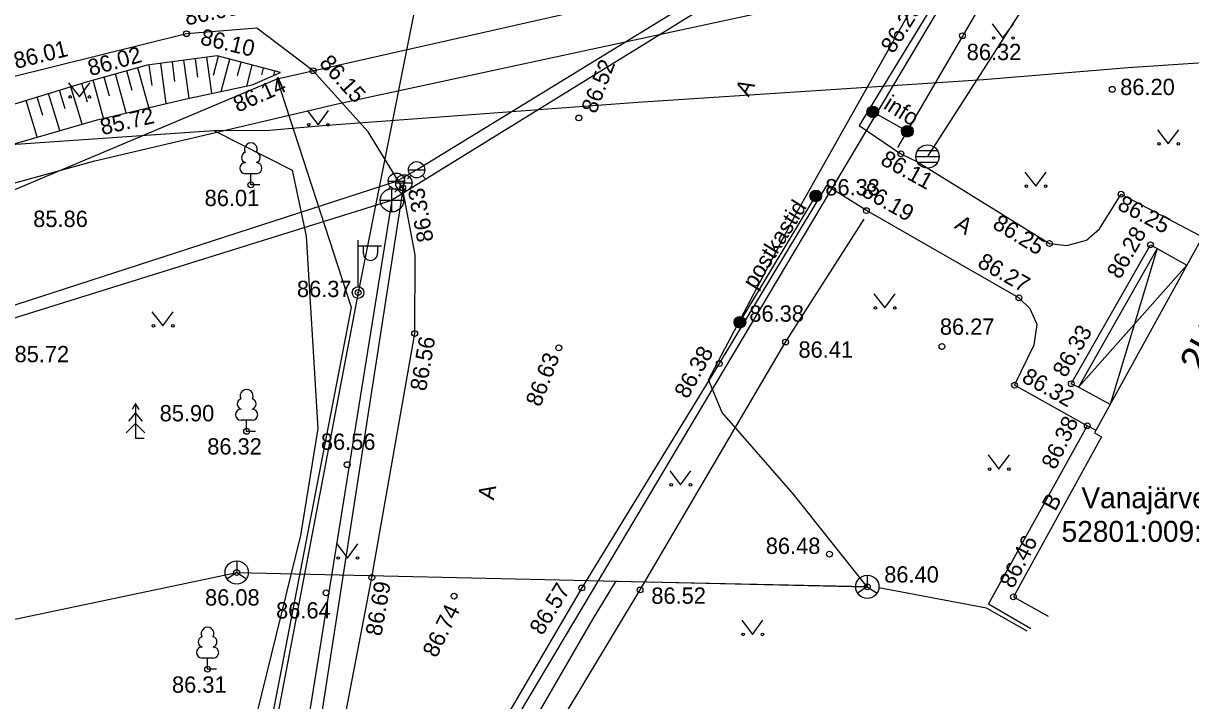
# Model space of a CAD drawing. Extents: x 648748 to 649126, y 6457789 to 6458252.
# Drawn here: x 648959.4 to 649009.5, y 6458116.3 to 6458145.4 of the extents above; entities that cross this region are included whole.
import ezdxf

# ---------------------------------------------------------------- set-up
doc = ezdxf.new("R2010")
doc.units = 0
for name, color, linetype in [('HALJASTUS', 7, 'Continuous'), ('HOONE', 7, 'Continuous'), ('HOONEDET', 7, 'Continuous'), ('KKAEV', 7, 'Continuous'), ('KORGUS-EH2000', 7, 'Continuous'), ('KTRASS', 7, 'Continuous'), ('MPOHULIIN', 7, 'Continuous'), ('PIIR', 7, 'Continuous'), ('POST', 7, 'Continuous'), ('PUU', 7, 'Continuous'), ('RAJATIS', 7, 'Continuous'), ('RELJEEF', 7, 'Continuous'), ('SIKAEV', 7, 'Continuous'), ('SITRASS', 7, 'Continuous'), ('SKKAEV', 7, 'Continuous'), ('SKTRASS', 7, 'Continuous'), ('TEE', 7, 'Continuous'), ('VKAEV', 7, 'Continuous'), ('VTRASS', 7, 'Continuous')]:
    doc.layers.add(name, color=color, linetype=linetype)

msp = doc.modelspace()

# ---------------------------------------------------------------- linework, layer by layer
at = {"layer": 'HALJASTUS'}
for p, q in [((649001.002, 6458145.339), (649001.465, 6458144.733)), ((649001.465, 6458144.733), (649001.911, 6458145.339)), ((648961.368, 6458142.814), (648961.832, 6458142.208)), ((648961.832, 6458142.208), (648962.277, 6458142.814)), ((648971.609, 6458141.622), (648972.072, 6458141.015)), ((648972.072, 6458141.015), (648972.518, 6458141.622)), ((649008.096, 6458140.802), (649008.56, 6458140.195)), ((649008.56, 6458140.195), (649009.005, 6458140.802)), ((649002.404, 6458138.987), (649002.868, 6458138.38)), ((649002.868, 6458138.38), (649003.313, 6458138.987)), ((648995.927, 6458133.763), (648996.391, 6458133.157)), ((648996.391, 6458133.157), (648996.836, 6458133.763)), ((648964.945, 6458132.995), (648965.409, 6458132.388)), ((648965.409, 6458132.388), (648965.854, 6458132.995)), ((649000.828, 6458126.848), (649001.292, 6458126.242)), ((649001.292, 6458126.242), (649001.737, 6458126.848)), ((648987.163, 6458126.174), (648987.626, 6458125.568)), ((648987.626, 6458125.568), (648988.072, 6458126.174)), ((648972.871, 6458123.035), (648973.335, 6458122.428)), ((648973.335, 6458122.428), (648973.78, 6458123.035)), ((648990.253, 6458119.76), (648990.716, 6458119.153)), ((648990.716, 6458119.153), (648991.162, 6458119.76))]:
    msp.add_line(p, q, dxfattribs=at)
for points in [[(648996.956, 6458140.042), (649002.443, 6458149.457), (649002.965, 6458149.902), (649013.289, 6458150.815), (649022.182, 6458151.711), (649026.81, 6458151.999), (649025.182, 6458145.874), (649024.817, 6458144.814)], [(648995.014, 6458108.651), (648992.555, 6458109.206), (648980.179, 6458111.553), (648985.889, 6458121.059), (648992.136, 6458131.694), (648995.514, 6458136.968)]]:
    msp.add_lwpolyline(points, dxfattribs=at)
for centre in [(649001.064, 6458144.733), (649001.893, 6458144.733), (648961.431, 6458142.208), (648962.26, 6458142.208), (648971.671, 6458141.015), (648972.5, 6458141.015), (649008.159, 6458140.195), (649008.988, 6458140.195), (649002.467, 6458138.38), (649003.296, 6458138.38), (648995.99, 6458133.157), (648996.819, 6458133.157), (648965.008, 6458132.388), (648965.837, 6458132.388), (649000.891, 6458126.242), (649001.72, 6458126.242), (648987.225, 6458125.568), (648988.054, 6458125.568), (648972.934, 6458122.428), (648973.763, 6458122.428), (648990.315, 6458119.153), (648991.144, 6458119.153)]:
    msp.add_circle(centre, 0.055, dxfattribs=at)
at = {"layer": 'HOONE'}
for points in [[(649018.559, 6458140.403), (649014.12, 6458142.878), (649010.319, 6458136.06), (649010.026, 6458136.209), (649005.386, 6458127.796), (649005.695, 6458127.625), (649001.912, 6458120.767), (649003.41, 6458119.934)], [(649006.059, 6458129.017), (649004.709, 6458129.762), (649004.395, 6458129.906), (649007.793, 6458135.863), (649008.077, 6458135.702), (649009.357, 6458134.996)]]:
    msp.add_lwpolyline(points, dxfattribs=at)
at = {"layer": 'HOONEDET'}
for p, q in [((649008.077, 6458135.702), (649004.709, 6458129.762)), ((649008.077, 6458135.702), (649006.059, 6458129.017)), ((649004.709, 6458129.762), (649009.357, 6458134.996))]:
    msp.add_line(p, q, dxfattribs=at)
msp.add_lwpolyline([(649005.449, 6458127.911), (649005.083, 6458128.103), (649000.84, 6458120.461), (649002.663, 6458119.409)], dxfattribs=at)
at = {"layer": 'KKAEV'}
for p, q in [((648975.244, 6458137.272), (648975.244, 6458138.272)), ((648974.744, 6458137.772), (648975.744, 6458137.772))]:
    msp.add_line(p, q, dxfattribs=at)
msp.add_circle((648975.244, 6458137.772), 0.5, dxfattribs=at)
at = {"layer": 'KORGUS-EH2000'}
for centre in [(648966.422, 6458144.919), (648999.73, 6458144.834), (648971.86, 6458143.333), (649006.156, 6458142.534), (648983.261, 6458141.306), (648997.086, 6458139.766), (648969.19, 6458138.438), (648975.702, 6458138.304), (649006.534, 6458138.037), (648995.602, 6458137.331), (649003.459, 6458135.922), (649007.793, 6458135.863), (648973.79, 6458133.816), (649002.15, 6458133.592), (648976.218, 6458132.059), (648992.136, 6458131.694), (648982.402, 6458131.443), (648998.845, 6458131.505), (648989.291, 6458130.767), (649001.962, 6458129.843), (649004.395, 6458129.906), (648969.007, 6458127.863), (649005.083, 6458128.103), (648973.323, 6458126.434), (648994.017, 6458122.596), (648968.579, 6458121.81), (648974.38, 6458121.59), (648995.643, 6458121.195), (648972.416, 6458120.936), (648977.908, 6458120.791), (648983.389, 6458121.145), (648985.889, 6458121.059), (649001.912, 6458120.767), (648967.331, 6458117.663)]:
    msp.add_circle(centre, 0.125, dxfattribs=at)
at = {"layer": 'KTRASS'}
for p, q in [((649000.53, 6458153.406), (648975.244, 6458137.772)), ((648957.262, 6458132.173), (648975.244, 6458137.772)), ((648975.244, 6458137.772), (648970.422, 6458107.842))]:
    msp.add_line(p, q, dxfattribs=at)
at = {"layer": 'MPOHULIIN'}
msp.add_lwpolyline([(648980.689, 6458168.372), (648973.79, 6458133.816), (648969.428, 6458110.939), (648964.567, 6458086.1), (648960.388, 6458067.751), (648949.192, 6458062.065)], dxfattribs=at)
at = {"layer": 'PIIR'}
for p, q in [((648970.31, 6458142.98), (649001.06, 6458149.93)), ((649001.06, 6458149.93), (648978.12, 6458111.43)), ((648952.09, 6458135.31), (648970.31, 6458142.98)), ((648973.5, 6458133.18), (648970.31, 6458142.98)), ((648965.52, 6458091.89), (648973.5, 6458133.18))]:
    msp.add_line(p, q, dxfattribs=at)
at = {"layer": 'POST'}
for p, q in [((648973.79, 6458134.066), (648973.79, 6458136.066)), ((648973.79, 6458135.816), (648974.79, 6458135.816)), ((648974.017, 6458135.495), (648974.017, 6458135.816)), ((648974.63, 6458135.495), (648974.63, 6458135.816))]:
    msp.add_line(p, q, dxfattribs=at)
for radius in [0.25, 0.0234]:
    msp.add_circle((648973.79, 6458133.816), radius, dxfattribs=at)
msp.add_arc((648974.323, 6458135.495), 0.306, 180, 0, dxfattribs=at)
at = {"layer": 'PUU'}
for p, q in [((648969.43, 6458138.913), (648968.949, 6458138.913)), ((648969.19, 6458138.438), (648969.19, 6458138.913)), ((648969.57, 6458138.438), (648969.19, 6458138.438)), ((648964.243, 6458129.05), (648964.093, 6458128.8)), ((648964.393, 6458128.8), (648964.243, 6458129.05)), ((648964.243, 6458129.05), (648964.243, 6458127.55)), ((648964.243, 6458128.65), (648963.943, 6458128.3)), ((648964.543, 6458128.3), (648964.243, 6458128.65)), ((648969.247, 6458128.338), (648968.767, 6458128.338)), ((648969.007, 6458127.863), (648969.007, 6458128.338)), ((648964.243, 6458128.2), (648963.843, 6458127.8)), ((648964.643, 6458127.8), (648964.243, 6458128.2)), ((648969.387, 6458127.863), (648969.007, 6458127.863)), ((648964.603, 6458127.55), (648964.243, 6458127.55)), ((648967.571, 6458118.138), (648967.091, 6458118.138)), ((648967.331, 6458117.663), (648967.331, 6458118.138)), ((648967.711, 6458117.663), (648967.331, 6458117.663))]:
    msp.add_line(p, q, dxfattribs=at)
for centre, radius, start, end in [((648969.02, 6458139.611), 0.233, 109.022, 253.142), ((648969.19, 6458139.958), 0.277, 332.58, 207.42), ((648969.36, 6458139.611), 0.233, 286.851, 70.986), ((648968.952, 6458139.151), 0.238, 90.002, 269.395), ((648969.427, 6458139.151), 0.238, 270.605, 89.998), ((648969.007, 6458129.383), 0.277, 332.58, 207.42), ((648968.769, 6458128.575), 0.238, 90.002, 269.395), ((648968.837, 6458129.035), 0.233, 109.022, 253.142), ((648969.177, 6458129.035), 0.233, 286.851, 70.986), ((648969.244, 6458128.575), 0.238, 270.605, 89.998), ((648967.331, 6458119.183), 0.277, 332.58, 207.42), ((648967.161, 6458118.835), 0.233, 109.022, 253.142), ((648967.501, 6458118.835), 0.233, 286.851, 70.986), ((648967.094, 6458118.375), 0.238, 90.002, 269.395), ((648967.569, 6458118.375), 0.238, 270.605, 89.998)]:
    msp.add_arc(centre, radius, start, end, dxfattribs=at)
at = {"layer": 'RAJATIS'}
for points in [[(648995.875, 6458141.567), (648997.359, 6458140.735)], [(648990.173, 6458132.543), (648993.432, 6458137.962)]]:
    msp.add_lwpolyline(points, dxfattribs=at)
for centre, radius in [((648995.875, 6458141.567), 0.25), ((648995.875, 6458141.567), 0.225), ((648995.875, 6458141.567), 0.2), ((648995.875, 6458141.567), 0.175), ((648995.875, 6458141.567), 0.15), ((648995.875, 6458141.567), 0.125), ((648995.875, 6458141.567), 0.1), ((648995.875, 6458141.567), 0.075), ((648995.875, 6458141.567), 0.05), ((648995.875, 6458141.567), 0.025), ((648997.359, 6458140.735), 0.25), ((648997.359, 6458140.735), 0.225), ((648997.359, 6458140.735), 0.2), ((648997.359, 6458140.735), 0.175), ((648997.359, 6458140.735), 0.15), ((648997.359, 6458140.735), 0.125), ((648997.359, 6458140.735), 0.1), ((648997.359, 6458140.735), 0.075), ((648997.359, 6458140.735), 0.05), ((648997.359, 6458140.735), 0.025), ((648993.432, 6458137.962), 0.25), ((648993.432, 6458137.962), 0.225), ((648993.432, 6458137.962), 0.2), ((648993.432, 6458137.962), 0.175), ((648993.432, 6458137.962), 0.15), ((648993.432, 6458137.962), 0.125), ((648993.432, 6458137.962), 0.1), ((648993.432, 6458137.962), 0.075), ((648993.432, 6458137.962), 0.05), ((648993.432, 6458137.962), 0.025), ((648990.173, 6458132.543), 0.25), ((648990.173, 6458132.543), 0.225), ((648990.173, 6458132.543), 0.2), ((648990.173, 6458132.543), 0.175), ((648990.173, 6458132.543), 0.15), ((648990.173, 6458132.543), 0.125), ((648990.173, 6458132.543), 0.1), ((648990.173, 6458132.543), 0.075), ((648990.173, 6458132.543), 0.05), ((648990.173, 6458132.543), 0.025)]:
    msp.add_circle(centre, radius, dxfattribs=at)
at = {"layer": 'RELJEEF'}
for p, q in [((648966.918, 6458143.049), (648966.81, 6458143.846)), ((648967.516, 6458142.355), (648967.305, 6458143.913)), ((648967.585, 6458143.139), (648967.799, 6458143.954)), ((648964.813, 6458141.751), (648964.343, 6458143.457)), ((648964.947, 6458142.694), (648964.828, 6458143.578)), ((648965.556, 6458141.924), (648965.323, 6458143.645)), ((648965.932, 6458142.875), (648965.819, 6458143.712)), ((648966.535, 6458142.148), (648966.314, 6458143.779)), ((648967.919, 6458142.44), (648968.283, 6458143.827)), ((648968.616, 6458143.128), (648968.767, 6458143.7)), ((648969.013, 6458142.671), (648969.25, 6458143.573)), ((648969.658, 6458143.157), (648969.734, 6458143.447)), ((648962.864, 6458141.296), (648962.415, 6458142.926)), ((648963.124, 6458142.234), (648962.897, 6458143.059)), ((648963.839, 6458141.523), (648963.379, 6458143.192)), ((648964.094, 6458142.481), (648963.861, 6458143.324)), ((648970.167, 6458143.127), (648970.217, 6458143.32)), ((648960.985, 6458140.768), (648960.5, 6458142.35)), ((648961.222, 6458141.702), (648960.978, 6458142.496)), ((648961.945, 6458141.046), (648961.456, 6458142.643)), ((648962.18, 6458141.987), (648961.934, 6458142.789)), ((648960.024, 6458140.49), (648959.544, 6458142.057)), ((648960.263, 6458141.416), (648960.022, 6458142.204))]:
    msp.add_line(p, q, dxfattribs=at)
for points in [[(648970.459, 6458143.256), (648967.735, 6458143.971), (648964.739, 6458143.566), (648962.077, 6458142.833), (648954.927, 6458140.643), (648946.77, 6458137.721), (648935.909, 6458133.554)], [(648936.543, 6458131.741), (648947.386, 6458136.41), (648955.51, 6458139.186), (648962.587, 6458141.231), (648966.349, 6458142.109), (648969.251, 6458142.721), (648970.459, 6458143.256)]]:
    msp.add_lwpolyline(points, dxfattribs=at)
at = {"layer": 'SIKAEV'}
for p, q in [((648968.579, 6458122.31), (648968.579, 6458121.81)), ((648968.579, 6458121.81), (648968.164, 6458121.535)), ((648968.579, 6458121.81), (648968.994, 6458121.535)), ((648995.643, 6458121.695), (648995.643, 6458121.195)), ((648995.643, 6458121.195), (648995.228, 6458120.92)), ((648995.643, 6458121.195), (648996.058, 6458120.92))]:
    msp.add_line(p, q, dxfattribs=at)
for centre in [(648968.579, 6458121.81), (648995.643, 6458121.195)]:
    msp.add_circle(centre, 0.5, dxfattribs=at)
at = {"layer": 'SITRASS'}
for p, q in [((648876.861, 6458102.566), (648968.579, 6458121.81)), ((648968.579, 6458121.81), (648995.643, 6458121.195))]:
    msp.add_line(p, q, dxfattribs=at)
for points in [[(648995.643, 6458121.195), (648992.459, 6458125.184), (648989.418, 6458128.665), (648988.834, 6458130.069), (648992.568, 6458137.175), (649000.571, 6458151.371), (649010.371, 6458153.481), (649021.569, 6458155.012), (649033.911, 6458156.878), (649048.154, 6458158.873), (649059.027, 6458160.391), (649071.774, 6458161.431), (649085.639, 6458163.321), (649085.929, 6458161.874)], [(648967.592, 6458140.769), (648969.985, 6458140.783), (648972.271, 6458140.981), (648985.8, 6458141.981), (649000.627, 6458142.952), (649006.835, 6458143.47), (649012.826, 6458143.87)], [(648863.975, 6458121.708), (648868.963, 6458118.276), (648873.908, 6458114.787), (648879.921, 6458111.046), (648881.11, 6458110.63), (648883.242, 6458110.955), (648895.055, 6458116.596), (648901.713, 6458119.167), (648915.597, 6458124.69), (648933.55, 6458131.654), (648947.17, 6458136.394), (648958.488, 6458140.137), (648967.592, 6458140.769)], [(648967.592, 6458140.769), (648970.954, 6458139.072), (648971.562, 6458136.232), (648972.057, 6458127.987), (648971.319, 6458123.389), (648968.181, 6458110.649), (648966.331, 6458099.547), (648965.537, 6458094.866), (648966.077, 6458091.823), (648966.11, 6458089.841), (648964.318, 6458080.667)], [(648995.643, 6458121.195), (648984.834, 6458121.422), (648983.821, 6458119.744), (648978.901, 6458111.244), (648976.485, 6458102.526), (648974.256, 6458092.094), (648972.583, 6458080.942), (648971.63, 6458075.06), (648971.122, 6458066.021), (648973.701, 6458061.391), (648978.778, 6458055.16), (648981.628, 6458053.906), (648983.341, 6458058.682), (648986.212, 6458060.495)], [(649002.504, 6458119.297), (649000.755, 6458120.284), (648996.14, 6458121.145)]]:
    msp.add_lwpolyline(points, dxfattribs=at)
at = {"layer": 'SKKAEV'}
for p, q in [((648998.656, 6458139.901), (648997.796, 6458139.901)), ((648997.726, 6458139.651), (648998.726, 6458139.651)), ((648998.656, 6458139.401), (648997.796, 6458139.401))]:
    msp.add_line(p, q, dxfattribs=at)
msp.add_circle((648998.226, 6458139.651), 0.5, dxfattribs=at)
at = {"layer": 'SKTRASS'}
for points in [[(648947.113, 6458135.218), (648950.496, 6458136.157), (648962.487, 6458139.467), (648972.91, 6458141.909), (649003.97, 6458148.61)], [(649003.97, 6458148.61), (648998.226, 6458139.651)]]:
    msp.add_lwpolyline(points, dxfattribs=at)
at = {"layer": 'TEE'}
for points in [[(649002.881, 6458151.593), (649001.287, 6458150.721), (648998.193, 6458145.731), (648995.296, 6458140.982), (648997.086, 6458139.766), (648997.79, 6458139.425)], [(648964.651, 6458078.174), (648966.451, 6458083.821), (648967.5, 6458089.655), (648970.461, 6458102.422), (648972.022, 6458109.308), (648974.38, 6458121.59), (648976.218, 6458132.059), (648976.233, 6458135.434), (648975.702, 6458138.304), (648974.226, 6458140.713), (648971.86, 6458143.333), (648969.445, 6458145.153), (648966.422, 6458144.919), (648958.871, 6458143.041), (648949.896, 6458140.146), (648946.296, 6458138.815), (648935.488, 6458134.684), (648924.063, 6458130.013), (648903.056, 6458121.74), (648892.363, 6458117.796), (648888.636, 6458116.575), (648879.911, 6458112.582)], [(648997.79, 6458139.425), (649003.459, 6458135.922), (649004.209, 6458135.841), (649005.052, 6458136.068), (649005.604, 6458136.544), (649006.534, 6458138.037), (649009.91, 6458136.257)], [(648995.602, 6458137.331), (648993.894, 6458138.414), (648989.291, 6458130.767), (648983.389, 6458121.145), (648978.301, 6458112.451)], [(649005.083, 6458128.103), (649001.962, 6458129.843), (649002.809, 6458131.568), (649002.935, 6458132.447), (649002.63, 6458133.124), (649002.15, 6458133.592), (648995.602, 6458137.331)]]:
    msp.add_lwpolyline(points, dxfattribs=at)
at = {"layer": 'VKAEV'}
for p, q in [((648976.055, 6458138.835), (648975.915, 6458138.695)), ((648975.952, 6458139.082), (648976.652, 6458139.082)), ((648976.55, 6458138.835), (648976.689, 6458138.695)), ((648975.187, 6458138.347), (648975.047, 6458138.207)), ((648975.084, 6458138.594), (648975.784, 6458138.594)), ((648975.403, 6458138.516), (648976.103, 6458138.516)), ((648975.682, 6458138.347), (648975.821, 6458138.207)), ((648975.506, 6458138.269), (648975.366, 6458138.129)), ((648976.001, 6458138.269), (648976.14, 6458138.129))]:
    msp.add_line(p, q, dxfattribs=at)
for centre in [(648976.302, 6458139.082), (648975.434, 6458138.594), (648975.753, 6458138.516)]:
    msp.add_circle(centre, 0.35, dxfattribs=at)
at = {"layer": 'VTRASS'}
for points in [[(648976.302, 6458139.082), (648997.673, 6458152.175), (649000.44, 6458153.871), (649019.143, 6458157.138), (649019.466, 6458157.178), (649028.03, 6458158.241), (649030.273, 6458158.52), (649062.346, 6458163.005)], [(648859.612, 6458137.039), (648866.748, 6458133.902), (648887.357, 6458125.656), (648899.553, 6458111.732), (648928.544, 6458121.558), (648956.932, 6458132.595), (648957.558, 6458132.798), (648975.434, 6458138.594), (648975.797, 6458138.798), (648976.302, 6458139.082)], [(648975.797, 6458138.798), (648975.753, 6458138.516), (648971.13, 6458108.715), (648971.04, 6458108.27), (648962.304, 6458064.78), (648962.245, 6458064.485), (648962.127, 6458064.182)]]:
    msp.add_lwpolyline(points, dxfattribs=at)

# ---------------------------------------------------------------- texts
at = {"layer": 'HOONE'}
msp.add_text('2H', height=1.2, rotation=61.0962, dxfattribs=at).set_placement((649010.028, 6458130.243))
at = {"layer": 'HOONEDET'}
msp.add_text('B', height=0.7, rotation=60.8927, dxfattribs=at).set_placement((649003.704, 6458124.399))
at = {"layer": 'KORGUS-EH2000'}
for s, rotation, p in [('86.08', 11.941, (648966.424, 6458145.27)), ('86.25', 57.6746, (648996.761, 6458144.03)), ('86.10', 346.5087, (648966.977, 6458144.47)), ('86.01', 13.9646, (648959.111, 6458143.406)), ('86.02', 15.3953, (648962.3, 6458143.096)), ('86.15', 312.0814, (648972.088, 6458143.625)), ('86.52', 68.9773, (648983.994, 6458141.452)), ('86.14', 23.8876, (648968.624, 6458141.529)), ('85.72', 13.1369, (648962.814, 6458140.564)), ('86.11', 331.0771, (648996.159, 6458139.342)), ('86.19', 330.2698, (648995.345, 6458137.997)), ('86.33', 100.4711, (648977.034, 6458136.046)), ('86.25', 332.2001, (649006.325, 6458137.411)), ('86.25', 328.6213, (649000.968, 6458136.614)), ('86.28', 60.3015, (649006.484, 6458134.35)), ('86.27', 330.2698, (649000.322, 6458134.947)), ('86.33', 60.3015, (649004.156, 6458130.129)), ('86.56', 80.0431, (648976.702, 6458129.559)), ('86.38', 60.9983, (648987.929, 6458129.216)), ('86.63', 68.9196, (648981.609, 6458128.878)), ('86.32', 330.8488, (649002.224, 6458130.015)), ('86.38', 64.4766, (649003.712, 6458126.18)), ('86.46', 62.7276, (649001.896, 6458121.082)), ('86.69', 80.0431, (648974.789, 6458119.051)), ('86.57', 58.4745, (648981.695, 6458119.075)), ('86.74', 63.8849, (648977.15, 6458118.112))]:
    msp.add_text(s, height=0.7, rotation=rotation, dxfattribs=at).set_placement(p)
for s, p in [('86.32', (648999.908, 6458143.787)), ('86.20', (649006.494, 6458142.288)), ('86.33', (648993.839, 6458137.985)), ('86.01', (648967.205, 6458137.525)), ('85.86', (648959.849, 6458136.628)), ('86.37', (648971.165, 6458133.623)), ('86.38', (648990.58, 6458132.566)), ('86.27', (648998.756, 6458132.006)), ('85.72', (648959.048, 6458130.828)), ('86.41', (648992.688, 6458131.021)), ('85.90', (648965.275, 6458128.292)), ('86.32', (648967.316, 6458126.869)), ('86.56', (648972.193, 6458127.069)), ('86.48', (648991.285, 6458122.603)), ('86.40', (648996.368, 6458121.376)), ('86.08', (648967.222, 6458120.39)), ('86.52', (648986.374, 6458120.465)), ('86.64', (648970.272, 6458119.836)), ('86.31', (648965.803, 6458116.651))]:
    msp.add_text(s, height=0.7, dxfattribs=at).set_placement(p)
at = {"layer": 'PIIR'}
for s, p in [('Vanajärve tn 2', (649004.831, 6458124.565)), ('52801:009:0678', (649003.981, 6458123.121))]:
    msp.add_text(s, height=0.9, dxfattribs=at).set_placement(p)
at = {"layer": 'RAJATIS'}
for s, rotation, p in [('info', 327.8515, (648996.291, 6458141.733)), ('postkastid', 57.9283, (648990.83, 6458133.924))]:
    msp.add_text(s, height=0.7, rotation=rotation, dxfattribs=at).set_placement(p)
at = {"layer": 'TEE'}
for rotation, p in [(61.5117, (648990.546, 6458142.177)), (327.7885, (648999.338, 6458136.599)), (80.0431, (648979.612, 6458124.89))]:
    msp.add_text('A', height=0.7, rotation=rotation, dxfattribs=at).set_placement(p)

doc.saveas('drawing.dxf')
